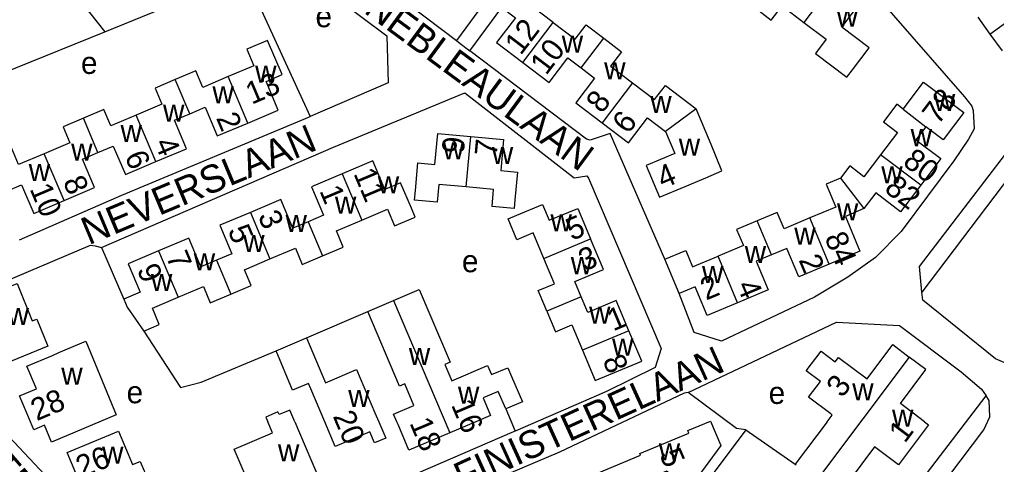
# Model space of a CAD drawing. Extents: x 157768 to 159790, y 387230 to 389604.
# Drawn here: x 158587.3 to 158763.5, y 388992.3 to 389072.5 of the extents above; entities that cross this region are included whole.
import ezdxf

# ---------------------------------------------------------------- set-up
doc = ezdxf.new("R2010")
doc.units = 0
for name, color, linetype in [('BLT_Basislijn', 7, 'Continuous'), ('BLT_Bebouwing', 7, 'Continuous'), ('BLT_Centroide', 7, 'Continuous'), ('BLT_Huisnummer', 7, 'Continuous'), ('BLT_Huisnummer_ tussenligend', 7, 'Continuous'), ('BLT_Onderverdeling_panden', 7, 'Continuous'), ('BLT_Straatnaam', 7, 'Continuous')]:
    doc.layers.add(name, color=color, linetype=linetype)

msp = doc.modelspace()

# ---------------------------------------------------------------- linework, layer by layer
at = {"layer": 'BLT_Basislijn'}
for p, q in [((158629.19, 389078), (158639.67, 389055.04)), ((158671.82, 389076.54), (158666.1, 389068.72)), ((158668.52, 389066.89), (158674.28, 389074.71)), ((158602.65, 389070.31), (158612.98, 389074.49)), ((158767.93, 389047), (158750.05, 389023.35)), ((158602.08, 389031.43), (158606.1, 389022.11)), ((158639.05, 389015.12), (158650.12, 389019.9)), ((158674.99, 389002.3), (158676.68, 388998.31)), ((158718.31, 388998.56), (158670.44, 388934.82)), ((158718.31, 388998.56), (158727.19, 388992.32))]:
    msp.add_line(p, q, dxfattribs=at)
for points in [[(158570.02, 389127.98), (158585.83, 389091.57), (158602.65, 389070.31)], [(158609.36, 389118.47), (158615.29, 389104.48), (158617.78, 389104.87), (158618.54, 389104.72), (158663.61, 389070.61), (158666.1, 389068.72)], [(158701.69, 389110.93), (158725.73, 389093.57), (158732.13, 389087.99), (158757.74, 389058.58), (158759.03, 389056.9), (158759.27, 389056.15), (158759.45, 389052.79), (158758.43, 389050.96), (158755.82, 389047.04), (158746.33, 389034.3), (158741.65, 389029.62), (158736.71, 389026.1), (158730.65, 389022.45), (158713.91, 389014.55), (158708.98, 389016.09), (158706.26, 389023.14)], [(158634.79, 389083.67), (158653.51, 389069.57), (158653.77, 389061.1), (158639.67, 389055.04)], [(158581.82, 389045.89), (158575.55, 389059.22), (158575.85, 389059.48), (158602.65, 389070.31)], [(158666.1, 389068.72), (158666.75, 389068.22), (158668.52, 389066.89)], [(158703.67, 389029.29), (158693.83, 389051.97), (158690.19, 389050.8), (158689.55, 389050.96), (158668.52, 389066.89)], [(158602.08, 389031.43), (158643.9, 389049.51), (158667.58, 389059.3), (158687.32, 389044), (158689.59, 389044.34), (158689.92, 389043.91), (158703.02, 389013.22), (158701.91, 389009.8), (158693.14, 389005.46), (158676.68, 388998.31)], [(158587.26, 389032.8), (158605.75, 389040.85), (158638.86, 389054.69), (158639.67, 389055.04)], [(158750.05, 389023.35), (158749.59, 389028), (158767.28, 389051.09)], [(158676.68, 388998.31), (158676.06, 388998.04), (158618.1, 388973.01), (158612.83, 388971.24), (158611.36, 388971.19), (158609.4, 388971.76), (158581.6, 389001.27), (158576.65, 389008.33), (158574.06, 389013.7), (158572.94, 389018.07), (158574.41, 389020.81), (158575.24, 389021.35), (158600.07, 389031.82), (158600.89, 389031.72), (158602.08, 389031.43)], [(158765.85, 389010.29), (158763.34, 389011.35), (158750.2, 389021.92), (158750.05, 389023.35)], [(158707.91, 389005.25), (158734.64, 389017.97), (158746.01, 389017.36), (158757.16, 389009.01), (158760.81, 389005.85), (158761.62, 389004.65)], [(158609.71, 389016.33), (158616.31, 389006.17), (158620.01, 389007.14), (158633.54, 389012.79)], [(158707.91, 389005.25), (158707.16, 389005.14), (158684.65, 388994.53), (158648.73, 388979.22), (158646.5, 388977.88), (158643.79, 388971.76), (158651.7, 388950.91), (158652.42, 388950.11)], [(158718.31, 388998.56), (158716.62, 388998.8), (158707.91, 389005.25)], [(158712.33, 388934.88), (158726.27, 388952.34), (158761.2, 388998.51), (158762.32, 389000.87), (158762.19, 389003.82), (158761.62, 389004.65)], [(158739.8, 388983.33), (158743.2, 388981.2), (158747.35, 388985.97), (158761.62, 389004.65)]]:
    msp.add_lwpolyline(points, dxfattribs=at)
at = {"layer": 'BLT_Bebouwing'}
for p, q in [((158760.11, 389072.94), (158762.3, 389069.91)), ((158762.3, 389069.91), (158764.5, 389066.87)), ((158706.26, 389023.14), (158703.67, 389029.29)), ((158654.74, 389021.87), (158659.37, 389023.83)), ((158650.12, 389019.9), (158654.74, 389021.87)), ((158633.54, 389012.79), (158639.05, 389015.12)), ((158669.58, 389000), (158664.88, 388998)), ((158732.96, 389000), (158727.19, 388992.32)), ((158727.19, 388992.32), (158727.38, 388992.18))]:
    msp.add_line(p, q, dxfattribs=at)
for points in [[(158683.54, 389071.97), (158679.59, 389074.98), (158681.57, 389077.58), (158678.34, 389080.04)], [(158728.77, 389072), (158732.78, 389068.96), (158730.86, 389066.42), (158736.52, 389062.13), (158737.52, 389063.45), (158740.54, 389067.43), (158735.63, 389071.16), (158739, 389075.61), (158734.24, 389079.21)], [(158674.28, 389074.71), (158676.73, 389072.85), (158673.33, 389068.39), (158678.07, 389064.78)], [(158720.46, 389076.01), (158719.62, 389074.91), (158722.88, 389072.44), (158724.82, 389075), (158728.77, 389072)], [(158683.54, 389071.97), (158687.49, 389068.96), (158689.48, 389071.57), (158692.67, 389069.14)], [(158628.44, 389053.87), (158633.94, 389056.2), (158631.74, 389061.38), (158634.62, 389062.6), (158632.01, 389068.76), (158628.28, 389067.18), (158629.54, 389064.19), (158624.9, 389062.23)], [(158692.67, 389069.14), (158695.84, 389066.72), (158693.89, 389064.14), (158697.86, 389061.12)], [(158678.07, 389064.78), (158682.8, 389061.18), (158686.19, 389065.63), (158688.6, 389063.79)], [(158624.9, 389062.23), (158620.33, 389060.29), (158619.07, 389063.26), (158615.37, 389061.7)], [(158688.6, 389063.79), (158691.02, 389061.96), (158687.62, 389057.5), (158692.36, 389053.89)], [(158615.37, 389061.7), (158611.72, 389060.15), (158612.95, 389057.24), (158608.33, 389055.28)], [(158697.86, 389061.12), (158701.84, 389058.09), (158703.79, 389060.65), (158709.34, 389056.42)], [(158746.7, 389056.39), (158750.35, 389061.23), (158757.59, 389055.77), (158753.86, 389050.82), (158750.75, 389053.17)], [(158746.7, 389056.39), (158745.52, 389057.28), (158743.11, 389054.09), (158745.64, 389052.18), (158742.59, 389048.14)], [(158608.33, 389055.28), (158603.75, 389053.34), (158602.5, 389056.3), (158598.79, 389054.73)], [(158611.88, 389046.9), (158617.38, 389049.23), (158615.2, 389054.37), (158617.98, 389055.55)], [(158617.98, 389055.55), (158620.76, 389056.72), (158622.95, 389051.54), (158628.44, 389053.87)], [(158703.8, 389052.31), (158705.46, 389048.35), (158700.33, 389046.2), (158702.72, 389040.5), (158707.33, 389042.43), (158711.09, 389044.01), (158713.99, 389045.22), (158712.04, 389049.98), (158709.34, 389056.42)], [(158598.79, 389054.73), (158595.12, 389053.17), (158596.35, 389050.29), (158591.74, 389048.34)], [(158692.36, 389053.89), (158697.1, 389050.28), (158700.53, 389054.79), (158703.8, 389052.31)], [(158667.85, 389042.33), (158662.9, 389042.79), (158662.61, 389039.58), (158658.52, 389039.96), (158658.68, 389041.7), (158659.15, 389046.68), (158662.18, 389046.39), (158662.7, 389051.98), (158668.7, 389051.42)], [(158750.75, 389053.17), (158748.98, 389050.83), (158753.44, 389047.46), (158749.83, 389042.67)], [(158668.7, 389051.42), (158674.59, 389050.88), (158674.07, 389045.28), (158677.09, 389045), (158676.63, 389040.03), (158676.48, 389038.46), (158672.52, 389038.83), (158672.8, 389041.87), (158667.85, 389042.33)], [(158591.74, 389048.34), (158587.1, 389046.37), (158585.88, 389049.26), (158582.21, 389047.71), (158582.88, 389046.13), (158584.83, 389041.52), (158587.65, 389042.72), (158589.84, 389037.56), (158595.32, 389039.88)], [(158595.32, 389039.88), (158600.81, 389042.21), (158598.62, 389047.36), (158601.41, 389048.54)], [(158601.41, 389048.54), (158604.19, 389049.72), (158606.38, 389044.57), (158611.88, 389046.9)], [(158649.01, 389036.35), (158653.67, 389038.32), (158654.92, 389035.35), (158658.63, 389036.91), (158657.97, 389038.49), (158656.02, 389043.1), (158653.19, 389041.9), (158651.01, 389047.06), (158645.48, 389044.73)], [(158742.59, 389048.14), (158739.6, 389044.18), (158737.03, 389046.12), (158735.36, 389043.91)], [(158645.48, 389044.73), (158639.94, 389042.39), (158642.12, 389037.24), (158639.35, 389036.07)], [(158735.36, 389043.91), (158732.8, 389042.84), (158734.53, 389038.72), (158729.86, 389036.76)], [(158749.83, 389042.67), (158746.21, 389037.88), (158741.72, 389041.27), (158739.59, 389038.44)], [(158639.35, 389036.07), (158636.58, 389034.9), (158634.4, 389040.05), (158628.91, 389037.74)], [(158628.91, 389037.74), (158623.42, 389035.42), (158625.58, 389030.3), (158622.79, 389029.13)], [(158681.85, 389029.46), (158679.93, 389034.04), (158677, 389032.82), (158675.42, 389036.58), (158677.01, 389037.24), (158681.62, 389039.18), (158682.82, 389036.32), (158687.98, 389038.48), (158690.28, 389032.99)], [(158729.86, 389036.76), (158725.21, 389034.81), (158723.97, 389037.75), (158720.34, 389036.23)], [(158739.59, 389038.44), (158736.24, 389037.03), (158738.88, 389030.74), (158733.35, 389028.42)], [(158641.94, 389029.93), (158645.68, 389031.51), (158644.45, 389034.43), (158649.01, 389036.35)], [(158720.34, 389036.23), (158716.63, 389034.67), (158717.84, 389031.8), (158713.27, 389029.88)], [(158622.79, 389029.13), (158620, 389027.96), (158617.84, 389033.1), (158612.36, 389030.79)], [(158688.59, 389022.5), (158687.42, 389025.29), (158692.61, 389027.46), (158690.28, 389032.99)], [(158612.36, 389030.79), (158606.88, 389028.48), (158609.04, 389023.35), (158606.1, 389022.11)], [(158632.44, 389029.36), (158637.04, 389031.3), (158638.27, 389028.38), (158641.94, 389029.93)], [(158703.67, 389029.29), (158707.46, 389030.88), (158708.69, 389027.96), (158713.27, 389029.88)], [(158733.35, 389028.42), (158727.83, 389026.11), (158725.67, 389031.25), (158722.91, 389030.1)], [(158625.37, 389023.02), (158629.05, 389024.57), (158627.84, 389027.42), (158632.44, 389029.36)], [(158682.41, 389019.91), (158682.01, 389020.85), (158680.84, 389023.64), (158683.78, 389024.87), (158681.85, 389029.46)], [(158722.91, 389030.1), (158720.15, 389028.94), (158722.32, 389023.77), (158716.81, 389021.45)], [(158586.82, 389024.94), (158589.58, 389018.19), (158590.38, 389018.51), (158592.38, 389013.6), (158584.91, 389010.55), (158583.48, 389014.05), (158583.9, 389014.23), (158583.29, 389015.73), (158580.59, 389014.63), (158577.87, 389021.28), (158586.82, 389024.94)], [(158615.87, 389022.45), (158620.44, 389024.38), (158621.67, 389021.46), (158625.37, 389023.02)], [(158659.37, 389023.83), (158664.93, 389010.74), (158663.99, 389010.35), (158665.24, 389007.4), (158671.69, 389010.14)], [(158716.81, 389021.45), (158711.3, 389019.14), (158709.12, 389024.34), (158706.26, 389023.14)], [(158606.1, 389022.11), (158606.71, 389020.64), (158609.71, 389016.33)], [(158609.71, 389016.33), (158612.48, 389017.52), (158611.23, 389020.49), (158615.87, 389022.45)], [(158697.21, 389016.4), (158694.91, 389021.87), (158689.76, 389019.71), (158688.59, 389022.5)], [(158655.34, 389000), (158654.76, 389001.37), (158658.43, 389002.93), (158656.77, 389006.84), (158655.84, 389006.44), (158650.12, 389019.9)], [(158682.41, 389019.91), (158683.95, 389016.24), (158686.88, 389017.47), (158688.81, 389012.88)], [(158639.05, 389015.12), (158642.46, 389007.04), (158648.08, 389009.41), (158651.37, 389001.63), (158652.06, 389000)], [(158688.81, 389012.88), (158691.1, 389007.41), (158699.5, 389010.93), (158697.21, 389016.4)], [(158589.27, 389000), (158587.29, 389004.65), (158590.33, 389005.94), (158588.6, 389010), (158593.2, 389011.96), (158594.36, 389012.46), (158599.24, 389014.53), (158604.73, 389001.26), (158593.06, 388996.29)], [(158732.96, 389000), (158733.87, 389001.21), (158733.61, 389001.41), (158729.61, 389004.41), (158731.73, 389007.24), (158729.16, 389009.16), (158731.85, 389012.74), (158734.41, 389010.81), (158735.01, 389011.61), (158740.15, 389007.74), (158744.78, 389013.91), (158747.77, 389011.66)], [(158642.32, 389000), (158639.82, 389005.92), (158639.4, 389006.91), (158636.54, 389005.7), (158633.54, 389012.79)], [(158750.54, 389000), (158746.16, 389003.29), (158750.77, 389009.41), (158747.77, 389011.66)], [(158671.69, 389010.14), (158672.4, 389008.49), (158675.36, 389009.75), (158676.03, 389008.18), (158677.99, 389003.57), (158674.99, 389002.3)], [(158674.99, 389002.3), (158673.64, 389005.48), (158670.89, 389004.32), (158672.24, 389001.13), (158669.58, 389000)], [(158636.95, 389000), (158636.06, 389002.11), (158634.09, 389001.28), (158633.88, 389001.77), (158631.69, 389000.85), (158632.05, 389000)], [(158593.06, 388996.29), (158591.75, 388999.36), (158589.88, 388998.56), (158589.27, 389000)], [(158636.95, 389000), (158639.83, 388993.19), (158641.78, 388988.58), (158634.37, 388985.45), (158634.85, 388984.3), (158631.21, 388982.76), (158629.27, 388987.37), (158626, 388995.08), (158632.9, 388998), (158632.05, 389000)], [(158652.06, 389000), (158653.32, 388997.03), (158651.3, 388996.18), (158650.44, 388998.2), (158644.2, 388995.56), (158642.32, 389000)], [(158664.88, 388998), (158657.52, 388994.88), (158655.56, 388999.48), (158655.34, 389000)], [(158711.89, 389000.09), (158713.76, 388995.69), (158708.12, 388988.02), (158703.99, 388991.06), (158697.31, 388988.13), (158701.26, 388979.11), (158697.97, 388974.86), (158693.31, 388986.05), (158691.39, 388990.67), (158699.31, 388993.97), (158699.18, 388994.28), (158707.99, 388997.95), (158707.81, 388998.4), (158711.89, 389000.09)], [(158750.54, 389000), (158751.27, 388999.45), (158745.83, 388992.21), (158741.52, 388995.45), (158734.82, 388986.53)], [(158608.46, 388988.49), (158603.85, 388986.55), (158602.48, 388989.81), (158598.52, 388988.15), (158595.88, 388994.43), (158600.49, 388996.36), (158605.12, 388998.31), (158607.66, 388992.27), (158609.04, 388992.85), (158610.51, 388989.35), (158608.46, 388988.49)]]:
    msp.add_lwpolyline(points, dxfattribs=at)
at = {"layer": 'BLT_Onderverdeling_panden'}
for p, q in [((158762.3, 389069.91), (158784.78, 389086.17)), ((158734.24, 389079.21), (158728.77, 389072)), ((158678.07, 389064.78), (158683.54, 389071.97)), ((158688.6, 389063.79), (158692.67, 389069.14)), ((158617.98, 389055.55), (158615.37, 389061.7)), ((158628.44, 389053.87), (158624.9, 389062.23)), ((158697.86, 389061.12), (158692.36, 389053.89)), ((158611.88, 389046.9), (158608.33, 389055.28)), ((158709.34, 389056.42), (158703.8, 389052.31)), ((158746.7, 389056.39), (158750.75, 389053.17)), ((158601.41, 389048.54), (158598.79, 389054.73)), ((158667.85, 389042.33), (158668.7, 389051.42)), ((158595.32, 389039.88), (158591.74, 389048.34)), ((158749.83, 389042.67), (158742.59, 389048.14)), ((158645.48, 389044.73), (158649.01, 389036.35)), ((158735.36, 389043.91), (158739.59, 389038.44)), ((158628.91, 389037.74), (158632.44, 389029.36)), ((158639.35, 389036.07), (158641.94, 389029.93)), ((158722.91, 389030.1), (158720.34, 389036.23)), ((158733.35, 389028.42), (158729.86, 389036.76)), ((158681.85, 389029.46), (158690.28, 389032.99)), ((158612.36, 389030.79), (158615.87, 389022.45)), ((158622.79, 389029.13), (158625.37, 389023.02)), ((158716.81, 389021.45), (158713.27, 389029.88)), ((158654.74, 389021.87), (158664.88, 388998)), ((158688.59, 389022.5), (158682.41, 389019.91)), ((158697.21, 389016.4), (158688.81, 389012.88)), ((158747.77, 389011.66), (158731.05, 388989.4))]:
    msp.add_line(p, q, dxfattribs=at)

# ---------------------------------------------------------------- texts
at = {"layer": 'BLT_Centroide'}
for s, p in [('e', (158640.66, 389071.14)), ('w', (158734.66, 389071.22)), ('w', (158685.08, 389066.56)), ('e', (158598.36, 389062.72)), ('w', (158629.77, 389061.12)), ('w', (158692.73, 389061.73)), ('w', (158622.07, 389057.41)), ('w', (158752.2, 389056.03)), ('w', (158613.16, 389054.09)), ('w', (158701.05, 389055.69)), ('w', (158605.49, 389050.44)), ('w', (158748.02, 389049.69)), ('w', (158596.58, 389047.09)), ('w', (158663.61, 389047.31)), ('w', (158706.19, 389048)), ('w', (158672.47, 389046.48)), ('w', (158588.93, 389043.41)), ('w', (158742.72, 389043)), ('w', (158651.9, 389041.19)), ('w', (158644.17, 389037.53)), ('w', (158734.72, 389036.33)), ('w', (158635.26, 389034.22)), ('w', (158683.05, 389034.31)), ('w', (158727.02, 389031.94)), ('w', (158627.61, 389030.58)), ('w', (158718.09, 389028.64)), ('w', (158618.7, 389027.28)), ('e', (158667.08, 389026.96)), ('w', (158686.72, 389026.61)), ('w', (158710.39, 389025)), ('w', (158610.98, 389023.55)), ('w', (158585.12, 389017.44)), ('w', (158690.01, 389017.69)), ('w', (158694.16, 389011.91)), ('w', (158657.5, 389010.25)), ('w', (158594.8, 389006.66)), ('e', (158606.59, 389003.33)), ('w', (158666.36, 389003.25)), ('e', (158722.41, 389003.21)), ('w', (158737.48, 389003.86)), ('w', (158646.56, 389002.67)), ('w', (158744.66, 388999.09)), ('w', (158602.16, 388992.44)), ('w', (158633.89, 388992.83)), ('w', (158702.58, 388993.06))]:
    msp.add_text(s, height=4, dxfattribs=at).set_placement(p)
at = {"layer": 'BLT_Huisnummer'}
for s, rotation, p in [('12', 52.7325, (158677.68, 389065.94)), ('13', 22.9597, (158629.14, 389057.15)), ('8', 52.7276, (158692.32, 389055.42)), ('78', 52.9599, (158752.99, 389053.38)), ('2', 292.9552, (158622.68, 389054.79)), ('9', 84.684, (158667.4, 389048.24)), ('7', 84.6863, (158673.33, 389047.8)), ('6', 292.9647, (158606.18, 389047.89)), ('80', 322.9609, (158746.39, 389046.43)), ('4', 22.7388, (158703.32, 389041.97)), ('11', 292.857, (158647.46, 389044.77)), ('10', 292.9636, (158589.05, 389042.01)), ('1', 292.8565, (158641.32, 389041.66)), ('5', 22.7625, (158686.89, 389032.6)), ('5', 292.8572, (158624.78, 389034.52)), ('84', 292.775, (158732.43, 389033.23)), ('2', 292.7769, (158727.77, 389029.19)), ('9', 292.8536, (158608.39, 389027.47)), ('2', 22.7707, (158711.13, 389021.84)), ('4', 292.764, (158716.57, 389024.59)), ('1', 22.7616, (158694.36, 389016.27)), ('8', 292.7568, (158692.39, 389011.11)), ('3', 53.0873, (158735.69, 389004.15)), ('28', 23.0737, (158590.37, 389000.08)), ('16', 293.0071, (158665.08, 389003.04)), ('20', 292.9334, (158643.74, 389001.01)), ('18', 293.0015, (158657.57, 388999.79)), ('1', 53.0909, (158746.97, 388995.98)), ('26', 22.8014, (158598.5, 388989.8)), ('5', 293.6467, (158702.62, 388994.14))]:
    msp.add_text(s, height=4, rotation=rotation, dxfattribs=at).set_placement(p)
at = {"layer": 'BLT_Huisnummer_ tussenligend'}
for s, rotation, p in [('10', 52.7276, (158682.27, 389062.34)), ('6', 52.7276, (158697.06, 389051.71)), ('4', 292.9552, (158611.55, 389050.27)), ('8', 292.9647, (158595.05, 389043.34)), ('82', 322.965, (158743.07, 389041.63)), ('3', 292.8565, (158630.22, 389037.12)), ('7', 292.8572, (158613.64, 389029.79)), ('3', 22.7546, (158689.15, 389027.07))]:
    msp.add_text(s, height=4, rotation=rotation, dxfattribs=at).set_placement(p)
at = {"layer": 'BLT_Straatnaam'}
for s, rotation, p in [('FONTAINEBLEAULAAN', 323.593, (158629.48, 389088.41)), ('NEVERSLAAN', 22.691, (158599.76, 389031.8)), ('FINISTERELAAN', 24.4517, (158667.12, 388987.55)), ('FINISTERELAAN', 310.8519, (158570.17, 389004.88))]:
    msp.add_text(s, height=5, rotation=rotation, dxfattribs=at).set_placement(p)

doc.saveas('drawing.dxf')
